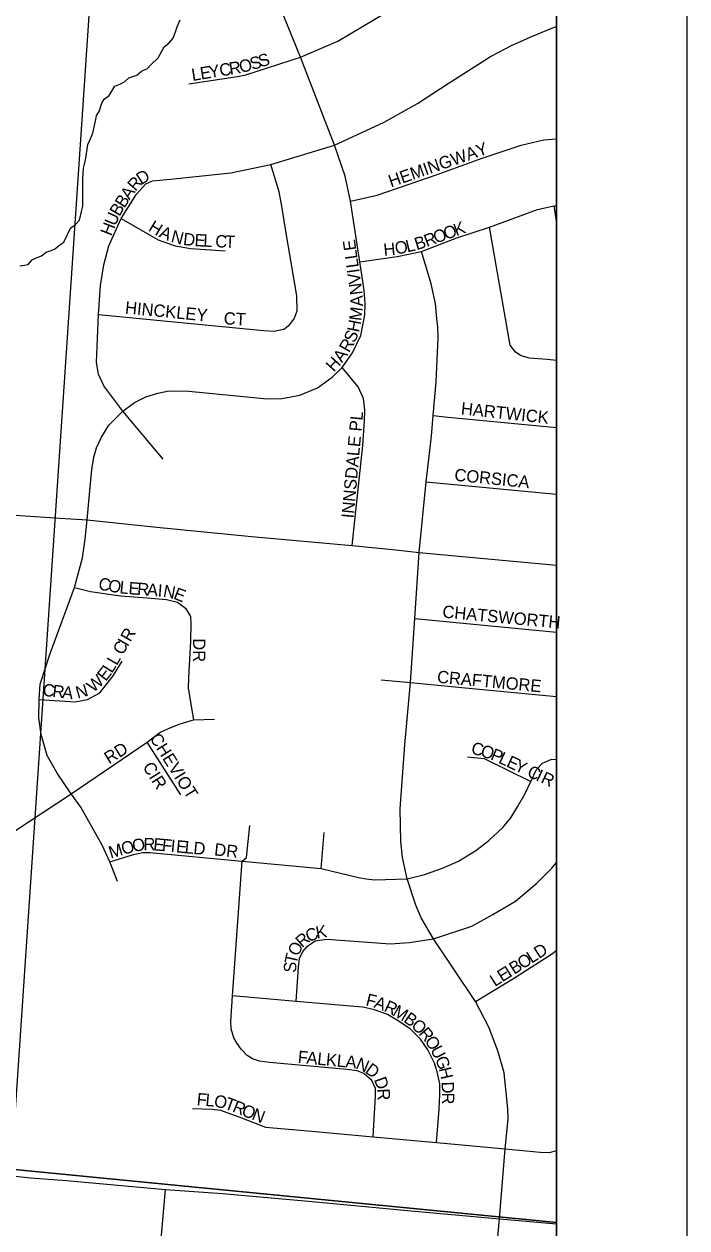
# Model space of a CAD drawing. Extents: x 8.5 to 81.5, y -1.2 to 22.4.
# Drawn here: x 55.845 to 56.353, y 16.084 to 17.008 of the extents above; entities that cross this region are included whole.
import ezdxf

# ---------------------------------------------------------------- set-up
doc = ezdxf.new("R2010")
doc.units = 0
for name, color, linetype in [('GM_X_City_Street', 7, 'Continuous'), ('GM_X_City_Street_Text', 7, 'Continuous'), ('GM_X_Corporation', 7, 'Continuous'), ('GM_X_County', 7, 'Continuous'), ('GM_X_Minor_River', 7, 'Continuous'), ('GM_X_Section', 7, 'Continuous'), ('SH_Data', 7, 'Continuous')]:
    doc.layers.add(name, color=color, linetype=linetype)

msp = doc.modelspace()

# ---------------------------------------------------------------- linework, layer by layer
at = {"layer": 'GM_X_City_Street'}
for points in [[(55.97072, 16.96168), (56.00806, 16.96739), (56.01448, 16.96871), (56.05639, 16.98234), (56.08516, 16.99442), (56.1228, 17.01706), (56.14666, 17.03348), (56.16665, 17.04562), (56.18471, 17.055), (56.20877, 17.0655), (56.22632, 17.07264), (56.25272, 17.08155)], [(55.91612, 16.34973), (55.91025, 16.36477), (55.90447, 16.37749), (55.88806, 16.40662), (55.88063, 16.41705), (55.86981, 16.43285), (55.8623, 16.44635), (55.8577, 16.46245), (55.85586, 16.47517), (55.85615, 16.48941), (55.85693, 16.50109), (55.86445, 16.52456), (55.88315, 16.57531), (55.88926, 16.59815), (55.89144, 16.61243), (55.89279, 16.62725), (55.89376, 16.63851), (55.8965, 16.66585), (55.89797, 16.67536), (55.89994, 16.68248), (55.90375, 16.69071), (55.90953, 16.69993), (55.92026, 16.71067), (55.92906, 16.71725), (55.93778, 16.72167), (55.94699, 16.7245), (55.95559, 16.72609), (55.97083, 16.72597), (56.0153, 16.72155), (56.03053, 16.7202), (56.0422, 16.72044), (56.05586, 16.72294), (56.06954, 16.7284), (56.08071, 16.73661), (56.08835, 16.74417), (56.09639, 16.75527), (56.10282, 16.76877), (56.10588, 16.78453), (56.10604, 16.79313), (56.10523, 16.80335), (56.10186, 16.82522), (56.09478, 16.87185), (56.09069, 16.89094), (56.08246, 16.91468), (56.05639, 16.98234), (56.0371, 17.03037)], [(55.9512, 16.67372), (55.92026, 16.71067), (55.90558, 16.73006), (55.90143, 16.73907), (55.90014, 16.74794), (55.90157, 16.78484), (55.903, 16.80714), (55.90572, 16.82302), (55.90958, 16.83747), (55.91888, 16.85849), (55.9306, 16.87722), (55.9379, 16.88509), (55.94305, 16.88738), (55.95686, 16.88856), (56.00311, 16.89353), (56.03357, 16.89982), (56.08246, 16.91468), (56.12054, 16.93241), (56.14609, 16.94667), (56.16954, 16.962), (56.20216, 16.98267), (56.21875, 16.99146), (56.23435, 16.99843), (56.24911, 17.00457), (56.25272, 17.00571)], [(56.09478, 16.87185), (56.11521, 16.87636), (56.162, 16.89244), (56.19577, 16.90482), (56.22552, 16.91479), (56.24305, 16.91881), (56.25272, 16.91957)], [(55.90157, 16.78484), (56.02802, 16.77244), (56.03603, 16.77211), (56.04362, 16.77343), (56.04808, 16.7769), (56.05171, 16.78152), (56.05394, 16.78754), (56.05352, 16.7991), (56.04502, 16.85034), (56.04213, 16.868), (56.03999, 16.87897), (56.03357, 16.89982)], [(56.10186, 16.82522), (56.13049, 16.82924), (56.14914, 16.83326), (56.17632, 16.84355), (56.20124, 16.85175), (56.23823, 16.86542), (56.25077, 16.86816), (56.25272, 16.8683)], [(56.25077, 16.86816), (56.2527, 16.85497), (56.25272, 16.85485)], [(55.91888, 16.85849), (55.94729, 16.84215), (55.96043, 16.83746), (55.97223, 16.83531), (55.99877, 16.8337)], [(56.25272, 16.74945), (56.24563, 16.75028), (56.23195, 16.7514), (56.22552, 16.75301), (56.22134, 16.75591), (56.21716, 16.76121), (56.20124, 16.85175)], [(56.20427, 16.03732), (56.20893, 16.09094), (56.21349, 16.14458), (56.21559, 16.16741), (56.21549, 16.1752), (56.21249, 16.20297), (56.20769, 16.21974), (56.20096, 16.23789), (56.19066, 16.25755), (56.1584, 16.30576), (56.14895, 16.32184), (56.14478, 16.33156), (56.13827, 16.35185), (56.13464, 16.36819), (56.13346, 16.38047), (56.13293, 16.40536), (56.13656, 16.45459), (56.14073, 16.50234), (56.14415, 16.55151), (56.14735, 16.60209), (56.1529, 16.65634), (56.15686, 16.69142), (56.15814, 16.70718), (56.16055, 16.73307), (56.16187, 16.76677), (56.16176, 16.77511), (56.16104, 16.78164), (56.15984, 16.79315), (56.15674, 16.80842), (56.14914, 16.83326)], [(56.09607, 16.60763), (56.10427, 16.68418), (56.10556, 16.70316), (56.10572, 16.71136), (56.10475, 16.72036), (56.10073, 16.72921), (56.08835, 16.74417)], [(56.15814, 16.70718), (56.16715, 16.70621), (56.25272, 16.69809)], [(56.1529, 16.65634), (56.25272, 16.6469)], [(55.82199, 16.63221), (55.84142, 16.63061), (55.87187, 16.62862)], [(55.87187, 16.62862), (55.89279, 16.62725), (55.94378, 16.62178), (56.01887, 16.61455), (56.09607, 16.60763), (56.12952, 16.60409), (56.14735, 16.60209), (56.25272, 16.59254)], [(55.88315, 16.57531), (55.89537, 16.57225), (55.91852, 16.56887), (55.93879, 16.56727), (55.95358, 16.56598), (55.96201, 16.56415), (55.96833, 16.55952), (55.97201, 16.5531), (55.97243, 16.54741), (55.97212, 16.53415), (55.97054, 16.50593), (55.97043, 16.49803), (55.97432, 16.47387)], [(56.14415, 16.55151), (56.25272, 16.54103)], [(55.85615, 16.48941), (55.88358, 16.48755), (55.89313, 16.48928), (55.90255, 16.49445), (55.91289, 16.50745), (55.91979, 16.51886)], [(56.11831, 16.50454), (56.14073, 16.50234), (56.18269, 16.49832), (56.25272, 16.49159)], [(55.8365, 16.38792), (55.88063, 16.41705), (55.93875, 16.4567), (55.94846, 16.46403), (55.95515, 16.4672), (55.96351, 16.4705), (55.97432, 16.47387), (55.99045, 16.47426)], [(55.96464, 16.41618), (55.93875, 16.4567)], [(55.91025, 16.36477), (55.9284, 16.37054), (55.93556, 16.37193), (55.94101, 16.37204), (56.01182, 16.36542), (56.07226, 16.35978), (56.10099, 16.35281), (56.10676, 16.35174), (56.11328, 16.3511), (56.13827, 16.35185), (56.15141, 16.35495), (56.16529, 16.35986), (56.17757, 16.36531), (56.19092, 16.37353), (56.20075, 16.38111), (56.21154, 16.39116), (56.21762, 16.39857), (56.22286, 16.40707), (56.22879, 16.41732), (56.23302, 16.42633), (56.23749, 16.43558), (56.24208, 16.44039), (56.24913, 16.44349), (56.25272, 16.44344)], [(56.18459, 16.44525), (56.1973, 16.44411), (56.23302, 16.42633)], [(56.11209, 16.15372), (56.11387, 16.18496), (56.11398, 16.19076), (56.11119, 16.19701), (56.10506, 16.20248), (56.09985, 16.20437), (56.09204, 16.20539), (56.03266, 16.21073), (56.02496, 16.21196), (56.01971, 16.21352), (56.01559, 16.21631), (56.0109, 16.22111), (56.00778, 16.22534), (56.00532, 16.22981), (56.00316, 16.23663), (56.00295, 16.24226), (56.0042, 16.26205), (56.01182, 16.36542), (56.01514, 16.36803), (56.01748, 16.3928)], [(56.07226, 16.35978), (56.07471, 16.38733)], [(56.05307, 16.2577), (56.05493, 16.28402), (56.05577, 16.29066), (56.05824, 16.29609), (56.06184, 16.30011), (56.06777, 16.30407), (56.07653, 16.30534), (56.12537, 16.30195), (56.13977, 16.3028), (56.1584, 16.30576), (56.18791, 16.3155), (56.20401, 16.3244), (56.22137, 16.33456), (56.2376, 16.3484), (56.24918, 16.35983), (56.25272, 16.36438)], [(56.19066, 16.25755), (56.22052, 16.27583), (56.24972, 16.29449), (56.25272, 16.29702)], [(56.16084, 16.14937), (56.16285, 16.17492), (56.16317, 16.18621), (56.16318, 16.19433), (56.16117, 16.20359), (56.15916, 16.2104), (56.15403, 16.22055), (56.14846, 16.22869), (56.14076, 16.23639), (56.13216, 16.24219), (56.12324, 16.24754), (56.1132, 16.25134), (56.10422, 16.25335), (56.09479, 16.25413), (56.05307, 16.2577), (56.0042, 16.26205)], [(55.97352, 16.1754), (55.98863, 16.17497), (55.9952, 16.17428), (56.01123, 16.16834), (56.02629, 16.16245), (56.02966, 16.16132), (56.06784, 16.15796), (56.11209, 16.15372), (56.16084, 16.14937), (56.21349, 16.14458), (56.24027, 16.14212), (56.24741, 16.14179), (56.25265, 16.14324), (56.25272, 16.14328)], [(55.72715, 16.13443), (55.73061, 16.13419), (55.7649, 16.1316), (55.84948, 16.12244), (55.87714, 16.1202), (55.95286, 16.11326), (55.99654, 16.11027), (56.06267, 16.10444), (56.13848, 16.09735), (56.20893, 16.09094), (56.25272, 16.08705)], [(55.94844, 16.0607), (55.95286, 16.11326)]]:
    msp.add_lwpolyline(points, dxfattribs=at)
at = {"layer": 'GM_X_Corporation'}
msp.add_line((56.25272, 15.06706), (56.25272, 20.11042), dxfattribs=at)
at = {"layer": 'GM_X_County'}
msp.add_lwpolyline([(54.08792, 21.25055), (49.45272, 21.25055), (49.45272, 14.45055), (56.25272, 14.45055), (56.25272, 19.11082)], dxfattribs=at)
at = {"layer": 'GM_X_Minor_River'}
for points in [[(55.84758, 16.82307), (55.8507, 16.82681), (55.85337, 16.8279), (55.85796, 16.82971), (55.86144, 16.83268), (55.8645, 16.83376), (55.86793, 16.83483), (55.8718, 16.83817), (55.87488, 16.84039), (55.88003, 16.85093), (55.88388, 16.85389), (55.88699, 16.85725), (55.88866, 16.86482), (55.88948, 16.86785), (55.88958, 16.87278), (55.88942, 16.88343), (55.88953, 16.88875), (55.89008, 16.8971), (55.89091, 16.90012), (55.89176, 16.90467), (55.89349, 16.91527), (55.89509, 16.91904), (55.89709, 16.92394), (55.89958, 16.93454), (55.90002, 16.93757), (55.90198, 16.94057), (55.90401, 16.94699), (55.90597, 16.94999), (55.90982, 16.95296), (55.91414, 16.96009), (55.91797, 16.96154), (55.92142, 16.96337), (55.9249, 16.96634), (55.93101, 16.9685), (55.93449, 16.97147), (55.93909, 16.97366), (55.9418, 16.97627), (55.94722, 16.98186), (55.95195, 16.99013), (55.95542, 16.9931), (55.95891, 16.99683), (55.96093, 17.00249), (55.96175, 17.00551), (55.96413, 17.01079)], [(55.84111, 16.82206), (55.84492, 16.82274), (55.84758, 16.82307)]]:
    msp.add_lwpolyline(points, dxfattribs=at)
at = {"layer": 'GM_X_Section'}
for p, q in [((56.25272, 16.08816), (56.25272, 17.09637)), ((56.25272, 15.08069), (56.25272, 16.08816))]:
    msp.add_line(p, q, dxfattribs=at)
msp.add_lwpolyline([(54.89877, 17.22287), (55.90174, 17.12832), (55.83452, 16.12902), (54.83971, 16.19386)], close=True, dxfattribs=at)
for points in [[(56.25272, 17.09637), (55.90174, 17.12832), (55.83452, 16.12902), (56.25272, 16.08816)], [(56.25272, 16.08816), (55.83452, 16.12902), (55.74333, 15.12296), (56.25272, 15.08069)]]:
    msp.add_lwpolyline(points, dxfattribs=at)
at = {"layer": 'SH_Data'}
for p, q in [((56.35272, 21.35055), (56.35272, 14.35055)), ((56.25272, 21.25055), (56.25272, 14.45055))]:
    msp.add_line(p, q, dxfattribs=at)

# ---------------------------------------------------------------- texts
at = {"layer": 'GM_X_City_Street_Text'}
for s, height, rotation, p in [('R', 0.00947, 9.34082, (56.00244, 16.96865)), ('O', 0.00947, 13.67649, (56.01061, 16.97003)), ('S', 0.00947, 17.71113, (56.0194, 16.97219)), ('S', 0.00947, 17.7355, (56.02576, 16.97422)), ('L', 0.00947, 9.33204, (55.97366, 16.96393)), ('E', 0.00947, 9.33062, (55.98024, 16.96501)), ('Y', 0.00947, 9.32789, (55.98682, 16.96609)), ('C', 0.00947, 9.3274, (55.99504, 16.96744)), ('HEMINGWAY', 0.00947, 19.23041, (56.12585, 16.88218)), ('R', 0.00947, 48.64274, (55.92991, 16.87878)), ('D', 0.00947, 32.902, (55.93435, 16.88397)), ('A', 0.00947, 55.64908, (55.9254, 16.87215)), ('B', 0.00947, 59.49013, (55.91759, 16.85954)), ('B', 0.00947, 56.93642, (55.92134, 16.86591)), ('U', 0.00947, 66.8674, (55.91446, 16.85216)), ('H', 0.00947, 68.56388, (55.91144, 16.84448)), ('H', 0.00947, 328.82635, (55.93912, 16.84948)), ('A', 0.00947, 336.17857, (55.94742, 16.84455)), ('N', 0.00947, 345.01675, (55.95655, 16.84066)), ('O', 0.00947, 20.2873, (56.16024, 16.83908)), ('O', 0.00947, 20.28746, (56.16806, 16.84196)), ('K', 0.00947, 20.28746, (56.17587, 16.84485)), ('D', 0.00947, 353.51387, (55.9661, 16.83822)), ('E', 0.00947, 356.94905, (55.975, 16.83723)), ('L', 0.00947, 357.46599, (55.98175, 16.83687)), ('C', 0.00947, 357.44926, (55.99091, 16.83646)), ('T', 0.00947, 357.46599, (55.99841, 16.83612)), ('E', 0.00947, 98.1417, (56.09932, 16.83444)), ('O', 0.00947, 11.01943, (56.12975, 16.83075)), ('L', 0.00947, 13.02162, (56.13828, 16.83241)), ('B', 0.00947, 17.06308, (56.14548, 16.8341)), ('R', 0.00947, 20.18749, (56.15318, 16.83648)), ('L', 0.00947, 98.1383, (56.10027, 16.82784)), ('H', 0.00947, 5.66928, (56.1205, 16.82978)), ('L', 0.00947, 98.11465, (56.10121, 16.82123)), ('I', 0.00947, 98.1502, (56.1018, 16.81711)), ('V', 0.00947, 98.02084, (56.10296, 16.80884)), ('N', 0.00947, 97.07508, (56.10401, 16.8004)), ('HINCKLEY', 0.00947, 354.36928, (55.92162, 16.78561)), ('A', 0.00947, 91.8415, (56.10436, 16.79113)), ('CT', 0.00947, 356.82151, (55.99738, 16.77728)), ('M', 0.00947, 82.62502, (56.10299, 16.77955)), ('H', 0.00947, 78.85004, (56.10127, 16.7707)), ('S', 0.00947, 66.02147, (56.09786, 16.76241)), ('R', 0.00947, 60.25183, (56.09367, 16.75496)), ('H', 0.00947, 47.82922, (56.08194, 16.74019)), ('A', 0.00947, 54.59187, (56.08829, 16.74731)), ('HARTWICK', 0.00947, 353.91197, (56.17913, 16.70811)), ('INNSDALE PL', 0.0094697, 84.86424, (56.09717, 16.62816)), ('CORSICA', 0.00947, 354.19663, (56.17412, 16.65727)), ('C', 0.00947, 349.32365, (55.90095, 16.57392)), ('O', 0.00947, 349.77361, (55.9084, 16.57251)), ('L', 0.00947, 353.95701, (55.91735, 16.57093)), ('E', 0.00947, 355.71008, (55.92429, 16.5702)), ('R', 0.00947, 355.64971, (55.93094, 16.5697)), ('A', 0.00947, 355.64657, (55.93842, 16.56913)), ('I', 0.00947, 355.65249, (55.94673, 16.5685)), ('N', 0.00947, 349.82614, (55.95063, 16.56821)), ('E', 0.00947, 338.63491, (55.95836, 16.56688)), ('CHATSWORTH', 0.00947, 354.58866, (56.16495, 16.55228)), ('I', 0.00947, 59.91349, (55.92389, 16.52934)), ('R', 0.00947, 59.92605, (55.92598, 16.53295)), ('C', 0.00947, 59.92605, (55.92013, 16.52285)), ('DR', 0.00947, 270, (55.97406, 16.53634)), ('L', 0.00947, 59.86996, (55.91553, 16.51492)), ('W', 0.00947, 41.20818, (55.89758, 16.49432)), ('E', 0.00947, 51.60181, (55.90702, 16.50281)), ('L', 0.00947, 58.02192, (55.91183, 16.50898)), ('CRAFTMORE', 0.00947, 354.68322, (56.16087, 16.50227)), ('C', 0.00947, 353.25753, (55.85837, 16.49227)), ('R', 0.00947, 353.25753, (55.86582, 16.49139)), ('A', 0.00947, 353.25185, (55.87327, 16.49051)), ('N', 0.00947, 16.01328, (55.88561, 16.48986)), ('CHEVIOT', 0.00947, 302.10506, (55.94046, 16.45978)), ('RD', 0.00947, 32.00292, (55.90967, 16.43951)), ('C', 0.00947, 345.75699, (56.18671, 16.44793)), ('O', 0.00947, 341.44767, (56.1938, 16.44613)), ('P', 0.00947, 337.13836, (56.20152, 16.44355)), ('L', 0.00947, 334.98371, (56.20758, 16.441)), ('E', 0.00947, 334.98371, (56.21362, 16.43818)), ('Y', 0.00947, 334.98371, (56.21966, 16.43536)), ('CIR', 0.00947, 302.27652, (55.93501, 16.43775)), ('C', 0.00947, 334.98371, (56.22948, 16.43077)), ('I', 0.00947, 334.98371, (56.23628, 16.4276)), ('R', 0.00947, 334.98371, (56.24005, 16.42584)), ('M', 0.00947, 16.52829, (55.91093, 16.36721)), ('O', 0.00947, 16.02944, (55.92049, 16.37005)), ('O', 0.00947, 9.99405, (55.92825, 16.37229)), ('R', 0.00947, 359.78141, (55.93601, 16.3737)), ('E', 0.00947, 354.99357, (55.9433, 16.37368)), ('F', 0.00947, 354.71899, (55.94993, 16.3731)), ('I', 0.00947, 354.70266, (55.95657, 16.37248)), ('E', 0.00947, 354.69178, (55.96072, 16.3721)), ('L', 0.00947, 354.73277, (55.96736, 16.37148)), ('D', 0.00947, 354.70266, (55.974, 16.37087)), ('DR', 0.00947, 353.98321, (55.98996, 16.36977)), ('C', 0.00947, 23.64189, (56.06271, 16.30288)), ('K', 0.00947, 10.08394, (56.06901, 16.30571)), ('R', 0.00947, 40.39321, (56.05762, 16.2984)), ('O', 0.00947, 63.73794, (56.05455, 16.29173)), ('L', 0.00947, 32.47747, (56.23361, 16.28658)), ('D', 0.00947, 32.45945, (56.23923, 16.29015)), ('S', 0.00947, 86.72015, (56.05299, 16.27953)), ('T', 0.00947, 77.60752, (56.05332, 16.28579)), ('B', 0.00947, 32.48423, (56.22026, 16.27807)), ('O', 0.00947, 32.48963, (56.22658, 16.2821)), ('L', 0.00947, 32.47747, (56.20549, 16.26868)), ('E', 0.00947, 32.47718, (56.21112, 16.27225)), ('I', 0.00947, 32.48573, (56.21674, 16.27583)), ('F', 0.00947, 346.23543, (56.10594, 16.25476)), ('A', 0.00947, 339.89927, (56.11215, 16.25325)), ('R', 0.00947, 334.7601, (56.11977, 16.25048)), ('M', 0.00947, 329.92976, (56.12637, 16.24738)), ('B', 0.00947, 324.4708, (56.13482, 16.2425)), ('O', 0.00947, 316.93233, (56.14067, 16.23835)), ('R', 0.00947, 310.32476, (56.14656, 16.23286)), ('O', 0.00947, 303.72039, (56.15124, 16.22738)), ('U', 0.00947, 297.09285, (56.15572, 16.22069)), ('F', 0.00947, 354.52859, (56.05407, 16.21058)), ('A', 0.00947, 354.54136, (56.06071, 16.20994)), ('L', 0.00947, 354.52859, (56.06901, 16.20915)), ('K', 0.00947, 354.54136, (56.07565, 16.20852)), ('L', 0.00947, 354.52859, (56.08394, 16.20772)), ('A', 0.00947, 354.51889, (56.09058, 16.20709)), ('N', 0.00947, 336.98507, (56.09813, 16.20648)), ('G', 0.00947, 292.06517, (56.15942, 16.21347)), ('D', 0.00947, 323.64158, (56.1053, 16.20351)), ('H', 0.00947, 282.60468, (56.16243, 16.20614)), ('D', 0.00947, 289.63766, (56.11271, 16.1978)), ('D', 0.00947, 272.36138, (56.16453, 16.19598)), ('F', 0.00947, 354.77341, (55.97659, 16.17811)), ('L', 0.00947, 354.7821, (55.98323, 16.17751)), ('O', 0.00947, 350.07053, (55.98966, 16.17693)), ('R', 0.00947, 272.35663, (56.11537, 16.19069)), ('R', 0.00947, 270.19431, (56.16487, 16.18775)), ('T', 0.00947, 339.86284, (55.99744, 16.17561)), ('R', 0.00947, 338.06778, (56.00363, 16.17334)), ('O', 0.00947, 338.05251, (56.01058, 16.17054)), ('N', 0.00947, 338.97243, (56.01847, 16.16736))]:
    msp.add_text(s, height=height, rotation=rotation, dxfattribs=at).set_placement(p)

doc.saveas('drawing.dxf')
